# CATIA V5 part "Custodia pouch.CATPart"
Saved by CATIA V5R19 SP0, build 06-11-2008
Part number: Custodia pouch
Bounding box of the stored display mesh (mm): x -1 to 45, y -8 to 17, z -5 to 63
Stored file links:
  C:\Users\sisca\Desktop\HELTEC_CASE\Custodia pouch.CATPart
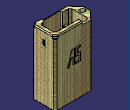
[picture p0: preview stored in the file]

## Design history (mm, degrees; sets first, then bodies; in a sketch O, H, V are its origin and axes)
Set1
  DatumCurve1 to DatumCurve13
  Sketch1 on end face of Pad1, origin (0, 0, 60), H (1, 0, 0), V (0, 1, 0)
    point P1 (42, 17)
    line L1 (45, -5) -> (42, -8)
    line L2 (42, 17) -> (45, 14)
    line L3 (45, -5) -> (45, 14)
    line L4 (42, 17) -> (16, 17)
    point P5 (42, 17)
    line L5 (16, 17) -> (16, 13)
    line L6 (35, -3) -> (35, -8)
    line L7 (42, -8) -> (35, -8)
    line L8 (16, 13) -> (39.1716, 13)
    line L9 (39.1716, 13) -> (41, 11.1716)
    line L10 (41, -1.1716) -> (41, 11.1716)
    line L11 (41, -1.1716) -> (39.1716, -3)
    line L12 (39.1716, -3) -> (35, -3)
    length L4 = 26
    distance L10 L3 = 4
    distance L6 L3 = 10
    vertical: L3 V, L5 V, L6 V
    coincidence: P5 L2, P1 P5
    horizontal: L4 H, L7 H
    fix: L3
  Sketch2 on face of Pad4, origin (45, 0, 0), H (0, 1, 0), V (0, 0, 1)
    point P2 (7, 47)
    point P3 (7, 47)
    point P4 (3, 47)
    point P6 (3, 47)
    line L1 (7, 57) -> (7, 47)
    line L2 (7, 47) -> (3, 47)
    line L3 (3, 57) -> (3, 47)
    line L4 (3.9, 54.5) -> (6.1, 54.5)
    line L5 (6.1, 54.5) -> (6.1, 49.5)
    line L6 (6.1, 49.5) -> (3.9, 49.5)
    line L7 (3.9, 49.5) -> (3.9, 54.5)
    line L8 (3, 57) -> (7, 57)
    reference projected line E1 (-5, 62) -> (14, 62) from edge [face of Pad4 | face of Chamfer5]
    length L5 = 5
    length L6 = 2.2
    distance L8 L4 = 2.5
    distance L5 L1 = 0.9
    distance L8 E1 = 5
    horizontal: L4 H, L6 H, L8 H
    vertical: L5 V, L7 V
    fix: L1
    coincidence: P2 P3, P4 P6
  Sketch3 on face of Pad4, origin (0, -8, 0), H (1, 0, 0), V (0, 0, 1)
    circle A1 centre (33, 2) radius 2.75
    reference projected circle E1 centre (33, 2) radius 3.25 from edge [face of Pocket6 from Sketch14.A1 | start face of Pocket6]
    circle A2 centre (16.5, 2) radius 2.75
    reference projected circle E2 centre (16.5, 2) radius 3.25 from edge [face of Pocket6 from Sketch14.A2 | start face of Pocket6]
    radius A1 = 2.75
    radius A2 = 2.75
    concentricity: A1 E1, A2 E2
  Sketch4 on end face of Pad1, origin (0, 0, 60), H (1, 0, 0), V (0, 1, 0)
    line L1 (-1, 8.5) -> (7, 8.5)
    line L2 (7, 8.5) -> (7, 0.5)
    line L3 (7, 0.5) -> (-1, 0.5)
    line L4 (-1, 0.5) -> (-1, 8.5)
    reference projected point E1 (7, 13) from vertex [end face of Pad1 | face of Pad1 from Sketch5.L8 | face of Chamfer1]
    reference projected line E2 (5, 17) -> (5, -8) from edge [face of Pad8 | face of Pad7]
    length L1 = 8
    distance L1 L3 = 8
    distance L1 E1 = 4.5
    distance L2 E2 = 2
    horizontal: L1 H, L3 H
    vertical: L2 V, L4 V
  DatumSurface1
  CLDGeom1 "Tessellation.1"
Body1 (main body)
  Sketch5 on xy-plane, origin (0, 0, 0), H (1, 0, 0), V (0, 1, 0)
    line L1 (7, 15) -> (43, 15)
    line L2 (43, 15) -> (43, -5)
    line L3 (43, -5) -> (7, -5)
    line L4 (45, -8) -> (45, 17)
    line L5 (5, 17) -> (45, 17)
    line L6 (45, -8) -> (5, -8)
    line L7 (5, 17) -> (5, -8)
    line L8 (7, 15) -> (7, -5)
    length L2 = 20
    distance L2 V = 43
    distance L4 V = 45
    distance L8 L7 = 2
    distance L6 H = 8
    distance L3 H = 5
    distance L6 L5 = 25
    length L5 = 40
    horizontal: L1 H, L3 H
    vertical: L2 V, L7 V, L8 V
  Pad1: profile Sketch5, direction (0, 0, 1), length 60, opposite side length 2
  Chamfer1: length 2, angle 45, on edge [face of Pad1 from Sketch5.L2 | face of Pad1 from Sketch5.L3]; edge [face of Pad1 from Sketch5.L1 | face of Pad1 from Sketch5.L2]; edge [face of Pad1 from Sketch5.L4 | face of Pad1 from Sketch5.L6]; edge [face of Pad1 from Sketch5.L5 | face of Pad1 from Sketch5.L4]; edge [face of Pad1 from Sketch5.L6 | face of Pad1 from Sketch5.L7]; edge [face of Pad1 from Sketch5.L7 | face of Pad1 from Sketch5.L5]; edge [face of Pad1 from Sketch5.L1 | face of Pad1 from Sketch5.L8]; edge [face of Pad1 from Sketch5.L8 | face of Pad1 from Sketch5.L3]
  Sketch6 on start face of Pad1, origin (0, 0, -2), H (1, 0, 0), V (0, -1, 0)
    line L1 (16.7724, 7.5) -> (20.7724, 7.5)
    line L2 (20.7724, 7.5) -> (20.7724, 3.7205)
    line L3 (20.7724, 3.7205) -> (16.7724, 3.7205)
    line L4 (16.7724, 3.7205) -> (16.7724, 7.5)
    reference projected line E1 (9.1241, 8) -> (42, 8) from edge [start face of Pad1 | face of Pad1 from Sketch5.L6]
    reference projected line E2 (16.7724, 1.2) -> (16.7724, 6.2) from edge of DatumCurve2
    distance L1 E1 = 0.5
    distance L4 L2 = 4
    distance L4 E2 = 0
    horizontal: L1 H, L3 H
    vertical: L2 V, L4 V
  Pocket1: profile Sketch6, direction (0, 0, 1), length 20
  Sketch7 on start face of Pad1, origin (0, 0, -2), H (1, 0, 0), V (0, -1, 0)
    line L1 (36.5953, 1.7) -> (36.5953, 3.2)
    line L2 (36.5953, 3.2) -> (43, 3.2)
    line L3 (43, 3.2) -> (43, -2.3)
    line L4 (43, -2.3) -> (36.5953, -2.3)
    point P5 (36.5953, -2.3)
    line L5 (36.5953, -2.3) -> (36.5953, -0.8)
    line L6 (36.5953, -0.8) -> (38.5564, -0.8)
    line L7 (38.5564, -0.8) -> (38.5564, 1.7)
    line L8 (38.5564, 1.7) -> (36.5953, 1.7)
    reference projected line E1 (43, 5) -> (43, -5) from edge [face of Pad1 from Sketch5.L2 | start face of Pad1]
    reference projected line E2 (38.0564, 1.2) -> (38.0564, -0.3) from edge of DatumCurve3
    reference projected line E3 (38.0564, 1.2) -> (36.6422, 1.2) from edge of DatumCurve4
    line L9 (14.0176, 1.7) -> (14.0176, 5)
    line L10 (14.0176, 5) -> (10.6128, 5)
    line L11 (10.6128, 5) -> (10.6128, -2.3)
    line L12 (10.6128, -2.3) -> (14.0176, -2.3)
    line L13 (14.0176, -2.3) -> (14.0176, -0.8)
    line L14 (14.0176, -0.8) -> (12.0564, -0.8)
    line L15 (12.0564, -0.8) -> (12.0564, 1.7)
    line L16 (12.0564, 1.7) -> (14.0176, 1.7)
    reference projected line E4 (13.9706, 1.2) -> (12.5564, 1.2) from edge of DatumCurve6
    reference projected line E5 (13.9706, -0.3) -> (12.5564, -0.3) from edge of DatumCurve7
    reference projected line E6 (12.5564, 1.2) -> (12.5564, -0.3) from edge of DatumCurve8
    reference projected line E7 (8.0777, 5) -> (40, 5) from edge [face of Pad1 from Sketch5.L3 | start face of Pad1]
    distance L2 L4 = 5.5
    distance L3 E1 = 0
    length L1 = 1.5
    length L5 = 1.5
    distance L7 E2 = 0.5
    distance L8 E3 = 0.5
    distance L16 E4 = 0.5
    distance L14 E5 = 0.5
    distance E6 L15 = 0.5
    distance L10 E7 = 0
    length L13 = 1.5
    vertical: L1 V, L3 V, L5 V, L7 V
    horizontal: L2 H, L4 H, L6 H, L8 H
    coincidence: P5 L1
  Pad2: profile Sketch7, direction (0, 0, 1), length 49
  Chamfer2: length 0.5, angle 45, on edge [face of Pad2 from Sketch7.L13 | face of Pad2 from Sketch7.L14]; edge [face of Pad2 from Sketch7.L16 | face of Pad2 from Sketch7.L9]; edge [face of Pad2 from Sketch7.L6 | face of Pad2 from Sketch7.L5]; edge [face of Pad2 from Sketch7.L1 | face of Pad2 from Sketch7.L8]
  Chamfer3: length 0.5, angle 45, on edge [face of Pad2 from Sketch7.L9 | face of Pad1 from Sketch5.L3]; edge [face of Pad1 from Sketch5.L3 | face of Pad2 from Sketch7.L11]; edge [face of Pad2 from Sketch7.L4 | face of Pad1 from Sketch5.L2]; edge [face of Chamfer1 | face of Pad2 from Sketch7.L2]
  Sketch8 on face of Pad1 from Sketch5.L6, origin (0, -8, 0), H (1, 0, 0), V (0, 0, 1)
    line L1 (17, 42) -> (31, 42)
    line L2 (31, 42) -> (31, 16)
    line L3 (31, 16) -> (17, 16)
    line L4 (17, 16) -> (17, 42)
    reference projected line E1 (9.1241, -2) -> (42, -2) from edge [face of Pad2 | face of Pad1 from Sketch5.L6]
    reference projected line E2 (45, -2) -> (45, 70) from edge [face of Pad1 from Sketch5.L4 | face of Chamfer1]
    length L2 = 26
    length L3 = 14
    distance L3 E1 = 18
    distance L2 E2 = 14
    horizontal: L1 H, L3 H
    vertical: L2 V, L4 V
  Pocket2: profile Sketch8, direction (0, 1, 0), length 2
  Sketch9 on face of Pad2, origin (0, 0, -2), H (1, 0, 0), V (0, -1, 0)
    projected line E1 (7, 8) -> (43, 8) from edge [face of Pad2 | face of Pad1 from Sketch5.L6]
    projected line E2 (43, 8) -> (45, 6) from edge [face of Pad2 | face of Chamfer1]
    projected line E3 (45, 6) -> (45, -15) from edge [face of Pad2 | face of Pad1 from Sketch5.L4]
    projected line E4 (45, -15) -> (43, -17) from edge [face of Pad2 | face of Chamfer1]
    projected line E5 (43, -17) -> (7, -17) from edge [face of Pad2 | face of Pad1 from Sketch5.L5]
    projected line E6 (5, 6) -> (7, 8) from edge [face of Pad2 | face of Chamfer1]
    projected line E7 (7, -17) -> (5, -15) from edge [face of Pad2 | face of Chamfer1]
    projected line E8 (5, -15) -> (5, 6) from edge [face of Pad2 | face of Pad1 from Sketch5.L7]
  Pad3: profile Sketch9, direction (0, 0, -1), length 1
  Sketch10 on end face of Pad3, origin (0, 0, -3), H (1, 0, 0), V (0, -1, 0)
    construction line L1 (21, 2.7) -> (28, 2.7)
    point P2 (28, 2.7)
    line L2 (21, 4.7) -> (28, 4.7)
    line L3 (28, 0.7) -> (21, 0.7)
    arc A1 centre (28, 2.7) radius 2 from (28, 4.7) to (28, 0.7) cw
    arc A2 centre (21, 2.7) radius 2 from (21, 0.7) to (21, 4.7) cw
    construction line L4 (39.1, 7) -> (10.4248, 7)
    construction line L5 (42, -5) -> (42, 5)
    reference projected line E1 (45, -14) -> (45, 5) from edge [face of Pad3 | end face of Pad3]
    distance L1 L2 = 2
    length L1 = 7
    distance L2 L4 = 2.3
    distance P2 E1 = 17
    horizontal: L1 H
    tangency: A1 L2, A2 L2, A1 L3, A2 L3
  Pocket3: profile Sketch10, direction (0, 0, 1), length 1
  Sketch11 on face of Pad1, origin (0, 0, 60), H (1, 0, 0), V (0, 1, 0)
    line L1 (46.0413, 7) -> (39.3818, 7)
    line L2 (39.3818, 7) -> (39.3818, 3)
    line L3 (39.3818, 3) -> (46.0413, 3)
    line L4 (46.0413, 3) -> (46.0413, 7)
    reference projected line E1 (45, 17) -> (5, 17) from edge [face of Pad3 | face of Pad1]
    length L2 = 4
    distance L1 E1 = 10
    horizontal: L1 H, L3 H
    vertical: L2 V, L4 V
  Pocket4: profile Sketch11, direction (0, 0, -1), length 13, opposite side length -3
  Sketch12 on start face of Pad1, origin (0, 0, -2), H (1, 0, 0), V (0, -1, 0)
    line L1 (15.2724, 7.5) -> (35.2724, 7.5)
    line L2 (35.2724, 7.5) -> (35.2724, 2.5)
    line L3 (35.2724, 2.5) -> (15.2724, 2.5)
    line L4 (15.2724, 2.5) -> (15.2724, 7.5)
    reference projected line E1 (9.1241, 8) -> (42, 8) from edge [start face of Pad1 | face of Pad1 from Sketch5.L6]
    reference projected line E2 (33.7724, 0) -> (33.7724, 5) from edge of DatumCurve1
    length L1 = 20
    distance L1 E1 = 0.5
    distance L2 E2 = 1.5
    length L2 = 5
    horizontal: L1 H, L3 H
    vertical: L2 V, L4 V
  Pad4: profile Sketch1, direction (0, 0, 1), length 3
  Chamfer4: length 2, angle 45, on edge [start face of Pad4 | face of Pad4 from Sketch1.L8]; edge [start face of Pad4 | face of Pad4 from Sketch1.L9]; edge [start face of Pad4 | face of Pad4 from Sketch1.L10]; edge [start face of Pad4 | face of Pad4 from Sketch1.L11]; edge [start face of Pad4 | face of Pad4 from Sketch1.L12]
  Chamfer5: length 1, angle 45, on edge [face of Pad4 | end face of Pad4] (x5)
  Chamfer6: length 0.5, angle 45, on edge [face of Pad1 from Sketch5.L2 | end face of Pocket4]
  Sketch13 on face of Pad4, origin (0, 17, 0), H (-1, 0, 0), V (0, 0, 1)
    line L1 (-31.8394, 27.8773) -> (-27.0005, 42.8773)
    line L2 (-27.0005, 42.8773) -> (-24.0005, 42.8773)
    line L3 (-24.0005, 42.8773) -> (-24.0005, 27.8773)
    line L4 (-24.0005, 27.8773) -> (-26.0005, 27.8773)
    line L5 (-26.0005, 27.8773) -> (-26.0005, 35.4379)
    line L6 (-26.0005, 35.4379) -> (-27.678, 35.4379)
    line L7 (-27.678, 35.4379) -> (-29.8394, 27.8773)
    line L8 (-29.8394, 27.8773) -> (-31.8394, 27.8773)
    line L9 (-22.9163, 42.8773) -> (-17.9991, 42.8773)
    line L10 (-17.9991, 42.8773) -> (-17.9991, 40.8773)
    line L11 (-17.9991, 40.8773) -> (-20.9163, 40.8773)
    line L12 (-20.9163, 40.8773) -> (-20.9163, 36.3773)
    line L13 (-20.9163, 36.3773) -> (-17.8989, 36.3773)
    line L14 (-17.8989, 36.3773) -> (-17.8989, 27.8773)
    line L15 (-17.8989, 27.8773) -> (-22.9163, 27.8773)
    line L16 (-22.9163, 27.8773) -> (-22.9163, 29.8773)
    line L17 (-22.9163, 29.8773) -> (-19.8989, 29.8773)
    line L18 (-19.8989, 29.8773) -> (-19.8989, 34.3773)
    line L19 (-19.8989, 34.3773) -> (-22.9163, 34.3773)
    line L20 (-22.9163, 34.3773) -> (-22.9163, 42.8773)
    length L10 = 2
    distance L12 L20 = 2
    distance L18 L14 = 2
    distance L13 L19 = 2
    distance L17 L15 = 2
    distance L9 L15 = 15
    distance L11 L13 = 4.5
    distance L2 L4 = 15
    distance L2 L8 = 15
    distance L5 L3 = 2
    length L8 = 2
    length L2 = 3
  Pocket5: profile Sketch13, direction (0, -1, 0), length 0.2
  Sketch14 on face of Pad4, origin (0, -8, 0), H (1, 0, 0), V (0, 0, 1)
    circle A1 centre (33, 2) radius 3.25
    point P1 (33, 2)
    reference projected line E1 (42, -3) -> (8, -3) from edge [face of Pad4 | end face of Pad3]
    reference projected line E2 (45, -2) -> (45, 70) from edge [face of Pad4 | face of Pad4]
    circle A2 centre (16.5, 2) radius 3.25
    point P2 (16.5, 2)
    reference projected line E3 (42, -3) -> (8, -3) from edge [face of Pad4 | end face of Pad3]
    reference projected line E4 (5, -2) -> (5, 70) from edge [face of Pad3 | face of Pad3]
    radius A1 = 3.25
    distance P1 E1 = 5
    distance P1 E2 = 12
    radius A2 = 3.25
    distance P2 E3 = 5
    distance P2 E4 = 11.5
  Pocket6: profile Sketch14, direction (0, 1, 0), length 3, opposite side length -2
  Sketch15 on end face of Pad1, origin (0, 0, 60), H (1, 0, 0), V (0, 1, 0)
    circle A1 centre (3, 4) radius 2.6
    point P1 (3, 4)
    reference projected point E1 (7, -3) from vertex [face of Pad1 from Sketch5.L8 | face of Chamfer1 | end face of Pad1]
    reference projected line E2 (-1, 9) -> (-1, 1) from edge [face of Pad7 from Sketch4.L4 | start face of Pad7]
    radius A1 = 2.6
    distance P1 E1 V = 7
    distance P1 E2 = 4
  Pad5: profile Sketch2, direction (-1, 0, 0), length 0.4
  Pocket7: profile Sketch3, direction (0, 1, 0), length 3
  Sketch16 on end face of Pad1, origin (0, 0, 60), H (1, 0, 0), V (0, 1, 0)
    point P1 (40, -5)
    point P2 (36.5, -5)
    point P4 (36.5, -5)
    point P5 (43, -2)
    point P6 (40, -5)
    point P7 (43, 12)
    point P8 (43, -2)
    point P9 (40, 15)
    point P10 (43, 12)
    point P12 (40, 15)
    line L1 (40, -5) -> (36.5, -5)
    line L2 (16, -5) -> (36.5, -5)
    line L3 (43, -2) -> (40, -5)
    line L4 (43, 12) -> (43, -2)
    line L5 (40, 15) -> (43, 12)
    line L6 (16, 15) -> (40, 15)
    line L7 (16, 13) -> (39.1716, 13)
    line L8 (39.1716, 13) -> (41, 11.1716)
    line L9 (41, 11.1716) -> (41, -1.1716)
    line L10 (41, -1.1716) -> (39.1716, -3)
    line L11 (39.1716, -3) -> (36.5, -3)
    line L12 (16, -3) -> (36.5, -3)
    line L13 (16, -3) -> (16, -5)
    line L14 (16, 13) -> (16, 15)
    distance L4 L14 = 27
    distance L4 L9 = 2
    distance L4 L13 = 27
    vertical: L13 V, L14 V
    coincidence: P1 P6, P2 P4, P5 P8, P7 P10, P9 P12
    fix: L4
  Pad6: profile Sketch16, direction (0, 0, -1), length 3, opposite side length -0.5
  Chamfer7: length 2, angle 45, on edge [end face of Pad6 | face of Pad6 from Sketch16.L7]; edge [end face of Pad6 | face of Pad6 from Sketch16.L8]; edge [end face of Pad6 | face of Pad6 from Sketch16.L9]; edge [end face of Pad6 | face of Pad6 from Sketch16.L10]; edge [end face of Pad6 | face of Pad6 from Sketch16.L11]
  Pad7: profile Sketch4, direction (0, 0, -1), length 8
  Pocket8: profile Sketch12, direction (0, 0, 1), length 77, opposite side length -13
  Pad8: profile end face of Pad3, direction along end face of Pad3, length 2
  Chamfer8: length 2, angle 45, on edge [face of Pad6 from Sketch16.L12 | face of Pocket8 from Sketch12.L2]; edge [face of Pad4 from Sketch1.L12 | face of Pocket8 from Sketch12.L2]
  Chamfer9: length 6, angle 45, on edge [face of Pad8 | face of Pad7 from Sketch4.L1]; edge [face of Pad8 | end face of Pad7]; edge [face of Pad7 from Sketch4.L3 | face of Pad8]
  Pocket9: profile Sketch15, direction (0, 0, -1), length 7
